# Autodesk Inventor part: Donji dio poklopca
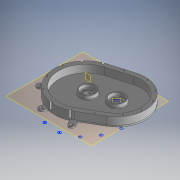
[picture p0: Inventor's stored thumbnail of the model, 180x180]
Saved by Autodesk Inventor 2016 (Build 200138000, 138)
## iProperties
Created: 2015-08
Part Number: Donji dio poklopca
Material: Generic
Document SubType Name: Modeling
Designer: stank
Density: 1 g/cm^3
Appearance: Default
Mass: 624.793 g
Surface Area: 1712.94 cm^2
Volume: 624.793 cm^3
Author: stank
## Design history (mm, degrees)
workplane "Work Plane1"
sketch "Sketch1" dims "d90" = 110
  geometry: L1 (-52.064, 118.882)-(-46.649, 108.689); L2 (-69.726, 109.498)-(-64.594, 99.838); L3 (-126.994, 39.663)-(-113.16, 35.428); L4 (-121.14, 58.787)-(-106.065, 54.173); L5 (-55.023, -107.864)-(-51.039, -94.851); L6 (-35.899, -113.718)-(-32.045, -101.129); L7 (48.505, -113.045)-(38.432, -94.085); L8 (66.167, -103.661)-(55.968, -84.464); L9 (-122.49, -36.299)-(-111.027, -30.209); L10 (-113.107, -53.961)-(-102.732, -48.449); L11 (-28.293, 54.626)-(47.33, 87.499) reference; L12 (89.587, -9.714)-(13.964, -42.586) reference; L13 (48.598, -88.799)-(119.152, -47.306); L14 (-38.458, 111.475)-(40.01, 134.76); L15 (-34.191, 97.094)-(44.277, 120.38); L16 (111.548, -34.377)-(40.994, -75.869); C1 r 4.5 at (-60.895, 114.19) reference; C2 r 4.5 at (-124.067, 49.225) reference; C3 r 4.5 at (-117.798, -45.13) reference; C4 r 4.5 at (-45.461, -110.791) reference; C5 r 4.5 at (57.336, -108.353) reference; A1 r 10 centre (-60.895, 114.19) between (-52.064, 118.882) and (-69.726, 109.498) reference; A2 r 10 centre (-124.067, 49.225) between (-121.14, 58.787) and (-126.994, 39.663) reference; A3 r 10 centre (-117.798, -45.13) between (-122.49, -36.299) and (-113.107, -53.961) reference; A4 r 10 centre (-45.461, -110.791) between (-55.023, -107.864) and (-35.899, -113.718) reference; A5 r 10 centre (57.336, -108.353) between (48.505, -113.045) and (66.167, -103.661) reference; A6 r 53 centre (-7.164, 6.02) between (-28.293, 54.626) and (13.964, -42.586) reference; A7 r 53 centre (68.459, 38.892) between (89.587, -9.714) and (47.33, 87.499) reference; A8 r 100 centre (68.459, 38.892) between (119.152, -47.306) and (40.01, 134.76); A9 r 95 centre (-7.164, 6.02) between (-34.191, 97.094) and (40.994, -75.869); A10 r 85 centre (68.459, 38.892) between (111.548, -34.377) and (44.277, 120.38)
  constraints: 28 end point, 10 tangent, 6 point on circle, 3 centre point, 2 coincident, 2 parallel, 1 point on line, 18 other
  dimensions: "d91" = 100 radius of A8; "d92" = 15 dimension on A9
extrude "Extrusion1" new body sketch "Sketch1" distance "d0" = 5; taper "d1" = 0 deg
sketch "Sketch2"
  geometry: L1 (-34.191, 97.094)-(44.277, 120.38) reference; L2 (111.548, -34.377)-(40.994, -75.869) reference; L3 (-38.458, 111.475)-(40.01, 134.76); L4 (119.152, -47.306)-(48.598, -88.799); A1 r 95 centre (-7.164, 6.02) between (-34.191, 97.094) and (40.994, -75.869) reference; A2 r 85 centre (68.459, 38.892) between (111.548, -34.377) and (44.277, 120.38) reference; A3 r 110 centre (-7.164, 6.02) between (-38.458, 111.475) and (48.598, -88.799); A4 r 100 centre (68.459, 38.892) between (119.152, -47.306) and (40.01, 134.76)
  constraints: 8 end point, 8 point on circle, 4 centre point, 13 other
  dimensions: "d93" = 15 radial gap between concentric circles of A1 A3
workplane "Work Plane2"
sketch "Sketch3"
  geometry: L1 (-48.598, -88.799)-(-119.152, -47.306); L2 (-40.01, 134.76)-(38.458, 111.475); L3 (38.458, 111.475)-(-40.01, 134.76) reference; L4 (-119.152, -47.306)-(-48.598, -88.799) reference; C1 r 7.5 at (7.41, 13.516) reference; A1 r 110 centre (7.164, 6.02) between (-48.598, -88.799) and (38.458, 111.475); A2 r 100 centre (-68.459, 38.892) between (-40.01, 134.76) and (-119.152, -47.306); A3 r 100 centre (-68.459, 38.892) between (-40.01, 134.76) and (-119.152, -47.306) reference; A4 r 110 centre (7.164, 6.02) between (89.616, 78.833) and (51.64, 106.628) reference; 1 further point
  constraints: 4 end point, 4 point on circle, 4 tangent, 2 centre point, 2 collinear, 2 concentric
extrude "Extrusion3" join sketch "Sketch3" distance "d4" = 5; taper "d5" = 0 deg
workplane "Work Plane4"
sketch "Sketch5"
  geometry: L1 (50, -31.888)-(50, 44.669); L2 (50, -15)-(49, -15); L3 (49, -15)-(49, -16); L4 (49, -16)-(50, -16); L5 (50, -23.5)-(37, -23.5); L6 (37, -23.5)-(37, -26.5); L7 (37, -26.5)-(50, -26.5); L8 (50, -7.5)-(50, 7.5) reference; L9 (50, 0)-(42.201, 0); L10 (50, -15)-(50, -16); L11 (50, -23.5)-(50, -26.5); 1 further point
  constraints: 20 end point, 4 perpendicular, 2 horizontal, 1 midpoint, 1 point on line
  dimensions: "d7" = 15 distance from line of L9.start L2; "d8" = 1 distance of L2.end L3.end; "d9" = 23.5 distance from line of L9.start L5; "d10" = 3 distance between parallel lines of L5 L7; "d12" = 1 distance from line of L2.start L3
workplane "Work Plane5"
sketch "Sketch6" dims "d7" = 15, "d8" = 1, "d9" = 23.5, "d10" = 3, "d12" = 1
  geometry: L1 (1, 13)-(0, 13); L2 (0, 13)-(0, 14); L3 (0, 14)-(1, 14); L4 (1, 23.5)-(-12, 23.5); L5 (-12, 23.5)-(-12, 27.5); L6 (-12, 27.5)-(1, 27.5); L7 (1, 27.5)-(1, 13); L8 (1, 42.026)-(1, -32.784); L9 (0, 0)-(-15.466, 0) reference; 1 further point
  constraints: 18 end point, 4 horizontal, 4 perpendicular, 2 point on line, 1 collinear
  dimensions: "d15" = 13 distance between parallel lines of L9 L1; "d16" = 1 distance of L1.end L2.end; "d17" = 1 distance of L2.end L3.end; "d18" = 13 distance of L4.start L4.end; "d19" = 4 distance of L4.end L5.end; "d20" = 23.5 distance from line of L9.end L4
revolve "Revolution2" stored, may be unused: angle "d14" = 90 deg
revolve "Revolution3" stored, may be unused: angle "d21" = 90 deg
fillet "Fillet1" dims "d22" = 2
fillet "Fillet4" dims "d44" = 2
extrude "Extrusion4" join sketch "Sketch2" distance "d78" = 26; taper "d79" = 0 deg
sketch "Sketch8"
  geometry: L1 (81.85, 31)-(0, 31) reference; L2 (81.85, 31)-(81.85, 0) reference; 1 further point
  dimensions: "d117" = 15 distance from line of L1 point (66.85, 16); "d118" = 15 distance from line of L2 point (66.85, 16)
chamfer "Chamfer3" distance "d87" = 2; stored, may be unused: second distance "d88" = 2, angle "d89" = 45 deg
sketch "Sketch10"
  geometry: L1 (-34.191, 97.094)-(44.277, 120.38) reference; L2 (111.548, -34.377)-(40.994, -75.869) reference; L3 (-36.325, 104.285)-(42.143, 127.57); L4 (115.35, -40.842)-(44.796, -82.334); L5 (-101.167, -34.842)-(-7.164, 6.02); L6 (-7.164, 6.02)-(-68.142, -76.369); L7 (-7.164, 6.02)-(-18.778, -95.82); L8 (-7.164, 6.02)-(33.698, -87.983); L9 (-7.164, 6.02)-(-109.004, 17.634); L10 (-7.164, 6.02)-(-89.553, 66.998); L11 (-7.164, 6.02)-(-48.026, 100.023); L12 (68.459, 38.892)-(78.94, 130.797); L13 (68.459, 38.892)-(123.488, 113.243); L14 (68.459, 38.892)-(153.291, 75.768); L15 (68.459, 38.892)-(160.363, 28.411); L16 (68.459, 38.892)-(142.81, -16.137); L17 (68.459, 38.892)-(-7.164, 6.02); C1 r 13 at (68.459, 38.892) reference; A1 r 95 centre (-7.164, 6.02) between (-34.191, 97.094) and (40.994, -75.869) reference; A2 r 85 centre (68.459, 38.892) between (111.548, -34.377) and (44.277, 120.38) reference; A3 r 92.5 centre (68.459, 38.892) between (115.35, -40.842) and (42.143, 127.57); 3 further points
  constraints: 30 end point, 7 point on circle, 2 midpoint, 1 centre point, 1 collinear, 1 perpendicular, 14 other
  dimensions: "d94" = 7.5 dimension on A1; "d95" = 30 deg angle of L11 L10; "d97" = 30 deg angle of L10 L9; "d102" = 30 deg angle of L7 L8; "d104" = 30 deg angle of L6 L7; "d105" = 30 deg angle of L5 L6; "d106" = 30 deg angle of L13 L14; "d107" = 30 deg angle of L12 L13; "d108" = 30 deg angle of L14 L15; "d109" = 30 deg angle of L15 L16
hole "Hole4" sketch "Sketch10" at (-101.167, -34.842), (-109.004, 17.634), (-89.553, 66.998), (-48.026, 100.023), (78.94, 130.797), (123.488, 113.243), (153.291, 75.768), (160.363, 28.411), (142.81, -16.137), (33.698, -87.983), (-18.778, -95.82), (-68.142, -76.369)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 diameter "d110" = 8; stored, may be unused: countersink angle "d114" = 90 deg, drill point angle "d116" = 118 deg; dims "d111" = 6, "d112" = 4, "d113" = 2, "d115" = 25
hole "Hole5" sketch "Sketch8" diameter "d119" = 20; stored, may be unused: countersink angle "d123" = 90 deg, drill point angle "d125" = 118 deg; dims "d120" = 6, "d121" = 4, "d122" = 2, "d124" = 25
body "Solid1"
node "Reference12"
node "Reference23"
node "Reference24"
node "Reference25"
node "Reference26"
node "Reference27"
node "Reference28"
node "Reference29"
node "Reference30"
node "Reference31"
node "Reference32"
node "Reference66"
node "Reference69"
node "Reference70"
node "Reference71"
node "Reference72"
node "Reference73"
node "Reference74"
node "Reference75"
node "Reference76"
node "Reference77"
node "Reference78"
node "Reference79"
